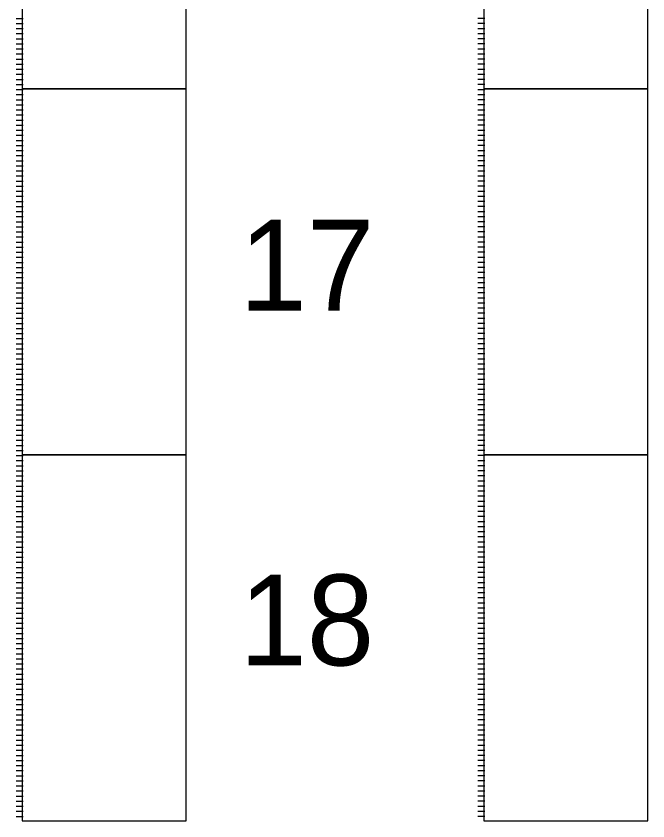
# Model space of a CAD drawing. Extents: x 12316 to 12541, y 1124 to 1850.
# Drawn here: x 12431.01 to 12465.81, y 1485.07 to 1529.4 of the extents above; entities that cross this region are included whole.
import ezdxf

# ---------------------------------------------------------------- set-up
doc = ezdxf.new("R2010")
doc.units = 0
doc.layers.add('SC_Scratch1', color=7, linetype='Continuous')
doc.layers.add('SH_Text', color=7, linetype='Continuous')

msp = doc.modelspace()

# ---------------------------------------------------------------- linework, layer by layer
at = {"layer": 'SC_Scratch1'}
for p, q in [((12431.394, 1529.257), (12431.01, 1529.257)), ((12456.827, 1529.269), (12456.443, 1529.269)), ((12431.394, 1528.977), (12431.01, 1528.977)), ((12456.827, 1528.989), (12456.443, 1528.989)), ((12456.827, 1528.709), (12456.443, 1528.709)), ((12431.394, 1528.697), (12431.01, 1528.697)), ((12431.394, 1528.417), (12431.01, 1528.417)), ((12456.827, 1528.429), (12456.443, 1528.429)), ((12431.394, 1528.137), (12431.01, 1528.137)), ((12431.394, 1527.857), (12431.01, 1527.857)), ((12456.827, 1528.149), (12456.443, 1528.149)), ((12456.827, 1527.869), (12456.443, 1527.869)), ((12431.394, 1527.577), (12431.01, 1527.577)), ((12456.827, 1527.589), (12456.443, 1527.589)), ((12431.394, 1527.297), (12431.01, 1527.297)), ((12431.394, 1527.017), (12431.01, 1527.017)), ((12456.827, 1527.309), (12456.443, 1527.309)), ((12456.827, 1527.029), (12456.443, 1527.029)), ((12431.394, 1526.737), (12431.01, 1526.737)), ((12456.827, 1526.749), (12456.443, 1526.749)), ((12431.394, 1526.457), (12431.01, 1526.457)), ((12431.394, 1526.177), (12431.01, 1526.177)), ((12456.827, 1526.469), (12456.443, 1526.469)), ((12456.827, 1526.189), (12456.443, 1526.189)), ((12431.394, 1525.897), (12431.01, 1525.897)), ((12431.394, 1525.617), (12431.01, 1525.617)), ((12456.827, 1525.909), (12456.443, 1525.909)), ((12456.827, 1525.629), (12456.443, 1525.629)), ((12431.394, 1525.337), (12431.01, 1525.337)), ((12456.827, 1525.349), (12456.443, 1525.349)), ((12431.394, 1525.057), (12431.01, 1525.057)), ((12431.394, 1524.777), (12431.01, 1524.777)), ((12456.827, 1525.069), (12456.443, 1525.069)), ((12456.827, 1524.789), (12456.443, 1524.789)), ((12431.394, 1524.497), (12431.01, 1524.497)), ((12456.827, 1524.509), (12456.443, 1524.509)), ((12431.394, 1524.217), (12431.01, 1524.217)), ((12431.394, 1523.937), (12431.01, 1523.937)), ((12456.827, 1524.229), (12456.443, 1524.229)), ((12456.827, 1523.949), (12456.443, 1523.949)), ((12431.394, 1523.657), (12431.01, 1523.657)), ((12456.827, 1523.669), (12456.443, 1523.669)), ((12456.827, 1523.389), (12456.443, 1523.389)), ((12431.394, 1523.377), (12431.01, 1523.377)), ((12431.394, 1523.097), (12431.01, 1523.097)), ((12456.827, 1523.109), (12456.443, 1523.109)), ((12431.394, 1522.817), (12431.01, 1522.817)), ((12431.394, 1522.537), (12431.01, 1522.537)), ((12456.827, 1522.829), (12456.443, 1522.829)), ((12456.827, 1522.549), (12456.443, 1522.549)), ((12431.394, 1522.257), (12431.01, 1522.257)), ((12456.827, 1522.269), (12456.443, 1522.269)), ((12431.394, 1521.977), (12431.01, 1521.977)), ((12431.394, 1521.697), (12431.01, 1521.697)), ((12456.827, 1521.989), (12456.443, 1521.989)), ((12456.827, 1521.709), (12456.443, 1521.709)), ((12431.394, 1521.417), (12431.01, 1521.417)), ((12456.827, 1521.429), (12456.443, 1521.429)), ((12431.394, 1521.137), (12431.01, 1521.137)), ((12431.394, 1520.857), (12431.01, 1520.857)), ((12456.827, 1521.149), (12456.443, 1521.149)), ((12456.827, 1520.869), (12456.443, 1520.869)), ((12431.394, 1520.577), (12431.01, 1520.577)), ((12431.394, 1520.297), (12431.01, 1520.297)), ((12456.827, 1520.589), (12456.443, 1520.589)), ((12456.827, 1520.309), (12456.443, 1520.309)), ((12431.394, 1520.017), (12431.01, 1520.017)), ((12456.827, 1520.029), (12456.443, 1520.029)), ((12431.394, 1519.737), (12431.01, 1519.737)), ((12431.394, 1519.457), (12431.01, 1519.457)), ((12456.827, 1519.749), (12456.443, 1519.749)), ((12456.827, 1519.469), (12456.443, 1519.469)), ((12431.394, 1519.177), (12431.01, 1519.177)), ((12456.827, 1519.189), (12456.443, 1519.189)), ((12431.394, 1518.897), (12431.01, 1518.897)), ((12431.394, 1518.617), (12431.01, 1518.617)), ((12456.827, 1518.909), (12456.443, 1518.909)), ((12456.827, 1518.629), (12456.443, 1518.629)), ((12431.394, 1518.337), (12431.01, 1518.337)), ((12456.827, 1518.349), (12456.443, 1518.349)), ((12456.827, 1518.069), (12456.443, 1518.069)), ((12431.394, 1518.057), (12431.01, 1518.057)), ((12431.394, 1517.777), (12431.01, 1517.777)), ((12456.827, 1517.789), (12456.443, 1517.789)), ((12431.394, 1517.497), (12431.01, 1517.497)), ((12431.394, 1517.217), (12431.01, 1517.217)), ((12456.827, 1517.509), (12456.443, 1517.509)), ((12456.827, 1517.229), (12456.443, 1517.229)), ((12431.394, 1516.937), (12431.01, 1516.937)), ((12456.827, 1516.949), (12456.443, 1516.949)), ((12431.394, 1516.657), (12431.01, 1516.657)), ((12431.394, 1516.377), (12431.01, 1516.377)), ((12456.827, 1516.669), (12456.443, 1516.669)), ((12456.827, 1516.389), (12456.443, 1516.389)), ((12431.394, 1516.097), (12431.01, 1516.097)), ((12456.827, 1516.109), (12456.443, 1516.109)), ((12431.394, 1515.817), (12431.01, 1515.817)), ((12431.394, 1515.537), (12431.01, 1515.537)), ((12456.827, 1515.829), (12456.443, 1515.829)), ((12456.827, 1515.549), (12456.443, 1515.549)), ((12431.394, 1515.257), (12431.01, 1515.257)), ((12431.394, 1514.977), (12431.01, 1514.977)), ((12456.827, 1515.269), (12456.443, 1515.269)), ((12456.827, 1514.989), (12456.443, 1514.989)), ((12431.394, 1514.697), (12431.01, 1514.697)), ((12456.827, 1514.709), (12456.443, 1514.709)), ((12431.394, 1514.417), (12431.01, 1514.417)), ((12431.394, 1514.137), (12431.01, 1514.137)), ((12456.827, 1514.429), (12456.443, 1514.429)), ((12456.827, 1514.149), (12456.443, 1514.149)), ((12431.394, 1513.857), (12431.01, 1513.857)), ((12456.827, 1513.869), (12456.443, 1513.869)), ((12431.394, 1513.577), (12431.01, 1513.577)), ((12431.394, 1513.297), (12431.01, 1513.297)), ((12456.827, 1513.589), (12456.443, 1513.589)), ((12456.827, 1513.309), (12456.443, 1513.309)), ((12431.394, 1513.017), (12431.01, 1513.017)), ((12456.827, 1513.029), (12456.443, 1513.029)), ((12456.827, 1512.749), (12456.443, 1512.749)), ((12431.394, 1512.737), (12431.01, 1512.737)), ((12431.394, 1512.457), (12431.01, 1512.457)), ((12456.827, 1512.469), (12456.443, 1512.469)), ((12431.394, 1512.177), (12431.01, 1512.177)), ((12431.394, 1511.897), (12431.01, 1511.897)), ((12456.827, 1512.189), (12456.443, 1512.189)), ((12456.827, 1511.909), (12456.443, 1511.909)), ((12431.394, 1511.617), (12431.01, 1511.617)), ((12456.827, 1511.629), (12456.443, 1511.629)), ((12431.394, 1511.337), (12431.01, 1511.337)), ((12431.394, 1511.057), (12431.01, 1511.057)), ((12456.827, 1511.349), (12456.443, 1511.349)), ((12456.827, 1511.069), (12456.443, 1511.069)), ((12431.394, 1510.777), (12431.01, 1510.777)), ((12456.827, 1510.789), (12456.443, 1510.789)), ((12431.394, 1510.497), (12431.01, 1510.497)), ((12431.394, 1510.217), (12431.01, 1510.217)), ((12456.827, 1510.509), (12456.443, 1510.509)), ((12456.827, 1510.229), (12456.443, 1510.229)), ((12431.394, 1509.937), (12431.01, 1509.937)), ((12431.394, 1509.657), (12431.01, 1509.657)), ((12456.827, 1509.949), (12456.443, 1509.949)), ((12456.827, 1509.669), (12456.443, 1509.669)), ((12431.394, 1509.377), (12431.01, 1509.377)), ((12456.827, 1509.389), (12456.443, 1509.389)), ((12431.394, 1509.097), (12431.01, 1509.097)), ((12431.394, 1508.817), (12431.01, 1508.817)), ((12456.827, 1509.109), (12456.443, 1509.109)), ((12456.827, 1508.829), (12456.443, 1508.829)), ((12431.394, 1508.537), (12431.01, 1508.537)), ((12456.827, 1508.549), (12456.443, 1508.549)), ((12431.394, 1508.257), (12431.01, 1508.257)), ((12431.394, 1507.977), (12431.01, 1507.977)), ((12456.827, 1508.269), (12456.443, 1508.269)), ((12456.827, 1507.989), (12456.443, 1507.989)), ((12431.394, 1507.697), (12431.01, 1507.697)), ((12456.827, 1507.709), (12456.443, 1507.709)), ((12456.827, 1507.429), (12456.443, 1507.429)), ((12431.394, 1507.417), (12431.01, 1507.417)), ((12431.394, 1507.137), (12431.01, 1507.137)), ((12456.827, 1507.149), (12456.443, 1507.149)), ((12431.394, 1506.857), (12431.01, 1506.857)), ((12431.394, 1506.577), (12431.01, 1506.577)), ((12456.827, 1506.869), (12456.443, 1506.869)), ((12456.827, 1506.589), (12456.443, 1506.589)), ((12431.394, 1506.297), (12431.01, 1506.297)), ((12456.827, 1506.309), (12456.443, 1506.309)), ((12431.394, 1506.017), (12431.01, 1506.017)), ((12431.394, 1505.737), (12431.01, 1505.737)), ((12456.827, 1506.029), (12456.443, 1506.029)), ((12456.827, 1505.749), (12456.443, 1505.749)), ((12431.394, 1505.457), (12431.01, 1505.457)), ((12456.827, 1505.469), (12456.443, 1505.469)), ((12431.394, 1505.177), (12431.01, 1505.177)), ((12431.394, 1504.897), (12431.01, 1504.897)), ((12456.827, 1505.189), (12456.443, 1505.189)), ((12456.827, 1504.909), (12456.443, 1504.909)), ((12431.394, 1504.617), (12431.01, 1504.617)), ((12431.394, 1504.337), (12431.01, 1504.337)), ((12456.827, 1504.629), (12456.443, 1504.629)), ((12456.827, 1504.349), (12456.443, 1504.349)), ((12431.394, 1504.057), (12431.01, 1504.057)), ((12456.827, 1504.069), (12456.443, 1504.069)), ((12431.394, 1503.777), (12431.01, 1503.777)), ((12431.394, 1503.497), (12431.01, 1503.497)), ((12456.827, 1503.789), (12456.443, 1503.789)), ((12456.827, 1503.509), (12456.443, 1503.509)), ((12431.394, 1503.217), (12431.01, 1503.217)), ((12456.827, 1503.229), (12456.443, 1503.229)), ((12431.394, 1502.937), (12431.01, 1502.937)), ((12431.394, 1502.657), (12431.01, 1502.657)), ((12456.827, 1502.949), (12456.443, 1502.949)), ((12456.827, 1502.669), (12456.443, 1502.669)), ((12431.394, 1502.377), (12431.01, 1502.377)), ((12456.827, 1502.389), (12456.443, 1502.389)), ((12456.827, 1502.109), (12456.443, 1502.109)), ((12431.394, 1502.097), (12431.01, 1502.097)), ((12431.394, 1501.817), (12431.01, 1501.817)), ((12456.827, 1501.829), (12456.443, 1501.829)), ((12431.394, 1501.537), (12431.01, 1501.537)), ((12431.394, 1501.257), (12431.01, 1501.257)), ((12456.827, 1501.549), (12456.443, 1501.549)), ((12456.827, 1501.269), (12456.443, 1501.269)), ((12431.394, 1500.977), (12431.01, 1500.977)), ((12456.827, 1500.989), (12456.443, 1500.989)), ((12431.394, 1500.697), (12431.01, 1500.697)), ((12431.394, 1500.417), (12431.01, 1500.417)), ((12456.827, 1500.709), (12456.443, 1500.709)), ((12456.827, 1500.429), (12456.443, 1500.429)), ((12431.394, 1500.137), (12431.01, 1500.137)), ((12456.827, 1500.149), (12456.443, 1500.149)), ((12431.394, 1499.857), (12431.01, 1499.857)), ((12431.394, 1499.577), (12431.01, 1499.577)), ((12456.827, 1499.869), (12456.443, 1499.869)), ((12456.827, 1499.589), (12456.443, 1499.589)), ((12431.394, 1499.297), (12431.01, 1499.297)), ((12431.394, 1499.017), (12431.01, 1499.017)), ((12456.827, 1499.309), (12456.443, 1499.309)), ((12456.827, 1499.029), (12456.443, 1499.029)), ((12431.394, 1498.737), (12431.01, 1498.737)), ((12456.827, 1498.749), (12456.443, 1498.749)), ((12431.394, 1498.457), (12431.01, 1498.457)), ((12431.394, 1498.177), (12431.01, 1498.177)), ((12456.827, 1498.469), (12456.443, 1498.469)), ((12456.827, 1498.189), (12456.443, 1498.189)), ((12431.394, 1497.897), (12431.01, 1497.897)), ((12456.827, 1497.909), (12456.443, 1497.909)), ((12431.394, 1497.617), (12431.01, 1497.617)), ((12431.394, 1497.337), (12431.01, 1497.337)), ((12456.827, 1497.629), (12456.443, 1497.629)), ((12456.827, 1497.349), (12456.443, 1497.349)), ((12431.394, 1497.057), (12431.01, 1497.057)), ((12456.827, 1497.069), (12456.443, 1497.069)), ((12456.827, 1496.789), (12456.443, 1496.789)), ((12431.394, 1496.777), (12431.01, 1496.777)), ((12431.394, 1496.497), (12431.01, 1496.497)), ((12456.827, 1496.509), (12456.443, 1496.509)), ((12431.394, 1496.217), (12431.01, 1496.217)), ((12431.394, 1495.937), (12431.01, 1495.937)), ((12456.827, 1496.229), (12456.443, 1496.229)), ((12456.827, 1495.949), (12456.443, 1495.949)), ((12431.394, 1495.657), (12431.01, 1495.657)), ((12456.827, 1495.669), (12456.443, 1495.669)), ((12431.394, 1495.377), (12431.01, 1495.377)), ((12431.394, 1495.097), (12431.01, 1495.097)), ((12456.827, 1495.389), (12456.443, 1495.389)), ((12456.827, 1495.109), (12456.443, 1495.109)), ((12431.394, 1494.817), (12431.01, 1494.817)), ((12456.827, 1494.829), (12456.443, 1494.829)), ((12431.394, 1494.537), (12431.01, 1494.537)), ((12431.394, 1494.257), (12431.01, 1494.257)), ((12456.827, 1494.549), (12456.443, 1494.549)), ((12456.827, 1494.269), (12456.443, 1494.269)), ((12431.394, 1493.977), (12431.01, 1493.977)), ((12431.394, 1493.697), (12431.01, 1493.697)), ((12456.827, 1493.989), (12456.443, 1493.989)), ((12456.827, 1493.709), (12456.443, 1493.709)), ((12431.394, 1493.417), (12431.01, 1493.417)), ((12456.827, 1493.429), (12456.443, 1493.429)), ((12431.394, 1493.137), (12431.01, 1493.137)), ((12431.394, 1492.857), (12431.01, 1492.857)), ((12456.827, 1493.149), (12456.443, 1493.149)), ((12456.827, 1492.869), (12456.443, 1492.869)), ((12431.394, 1492.577), (12431.01, 1492.577)), ((12456.827, 1492.589), (12456.443, 1492.589)), ((12431.394, 1492.297), (12431.01, 1492.297)), ((12431.394, 1492.017), (12431.01, 1492.017)), ((12456.827, 1492.309), (12456.443, 1492.309)), ((12456.827, 1492.029), (12456.443, 1492.029)), ((12431.394, 1491.737), (12431.01, 1491.737)), ((12456.827, 1491.749), (12456.443, 1491.749)), ((12456.827, 1491.469), (12456.443, 1491.469)), ((12431.394, 1491.457), (12431.01, 1491.457)), ((12431.394, 1491.177), (12431.01, 1491.177)), ((12456.827, 1491.189), (12456.443, 1491.189)), ((12431.394, 1490.897), (12431.01, 1490.897)), ((12431.394, 1490.617), (12431.01, 1490.617)), ((12456.827, 1490.909), (12456.443, 1490.909)), ((12456.827, 1490.629), (12456.443, 1490.629)), ((12431.394, 1490.337), (12431.01, 1490.337)), ((12456.827, 1490.349), (12456.443, 1490.349)), ((12431.394, 1490.057), (12431.01, 1490.057)), ((12431.394, 1489.777), (12431.01, 1489.777)), ((12456.827, 1490.069), (12456.443, 1490.069)), ((12456.827, 1489.789), (12456.443, 1489.789)), ((12431.394, 1489.497), (12431.01, 1489.497)), ((12456.827, 1489.509), (12456.443, 1489.509)), ((12431.394, 1489.217), (12431.01, 1489.217)), ((12431.394, 1488.937), (12431.01, 1488.937)), ((12456.827, 1489.229), (12456.443, 1489.229)), ((12456.827, 1488.949), (12456.443, 1488.949)), ((12431.394, 1488.657), (12431.01, 1488.657)), ((12431.394, 1488.377), (12431.01, 1488.377)), ((12456.827, 1488.669), (12456.443, 1488.669)), ((12456.827, 1488.389), (12456.443, 1488.389)), ((12431.394, 1488.097), (12431.01, 1488.097)), ((12456.827, 1488.109), (12456.443, 1488.109)), ((12431.394, 1487.817), (12431.01, 1487.817)), ((12431.394, 1487.537), (12431.01, 1487.537)), ((12456.827, 1487.829), (12456.443, 1487.829)), ((12456.827, 1487.549), (12456.443, 1487.549)), ((12431.394, 1487.257), (12431.01, 1487.257)), ((12456.827, 1487.269), (12456.443, 1487.269)), ((12431.394, 1486.977), (12431.01, 1486.977)), ((12431.394, 1486.697), (12431.01, 1486.697)), ((12456.827, 1486.989), (12456.443, 1486.989)), ((12456.827, 1486.709), (12456.443, 1486.709)), ((12431.394, 1486.417), (12431.01, 1486.417)), ((12456.827, 1486.429), (12456.443, 1486.429)), ((12456.827, 1486.149), (12456.443, 1486.149)), ((12431.394, 1486.137), (12431.01, 1486.137)), ((12431.394, 1485.857), (12431.01, 1485.857)), ((12456.827, 1485.869), (12456.443, 1485.869)), ((12431.394, 1485.577), (12431.01, 1485.577)), ((12431.394, 1485.297), (12431.01, 1485.297)), ((12456.827, 1485.589), (12456.443, 1485.589)), ((12456.827, 1485.309), (12456.443, 1485.309))]:
    msp.add_line(p, q, dxfattribs=at)
for points in [[(12465.813, 1545.559), (12456.77, 1545.559), (12456.77, 1525.399), (12465.813, 1525.399)], [(12440.38, 1545.547), (12431.337, 1545.547), (12431.337, 1525.387), (12440.38, 1525.387)], [(12440.38, 1525.387), (12431.337, 1525.387), (12431.337, 1505.227), (12440.38, 1505.227)], [(12465.813, 1525.399), (12456.77, 1525.399), (12456.77, 1505.239), (12465.813, 1505.239)], [(12440.38, 1505.227), (12431.337, 1505.227), (12431.337, 1485.067), (12440.38, 1485.067)], [(12465.813, 1505.239), (12456.77, 1505.239), (12456.77, 1485.079), (12465.813, 1485.079)]]:
    msp.add_lwpolyline(points, close=True, dxfattribs=at)

# ---------------------------------------------------------------- texts
at = {"layer": 'SH_Text'}
for s, p in [('17', (12443.304, 1513.18)), ('18', (12443.304, 1493.635))]:
    msp.add_text(s, height=5, dxfattribs=at).set_placement(p)

doc.saveas('drawing.dxf')
